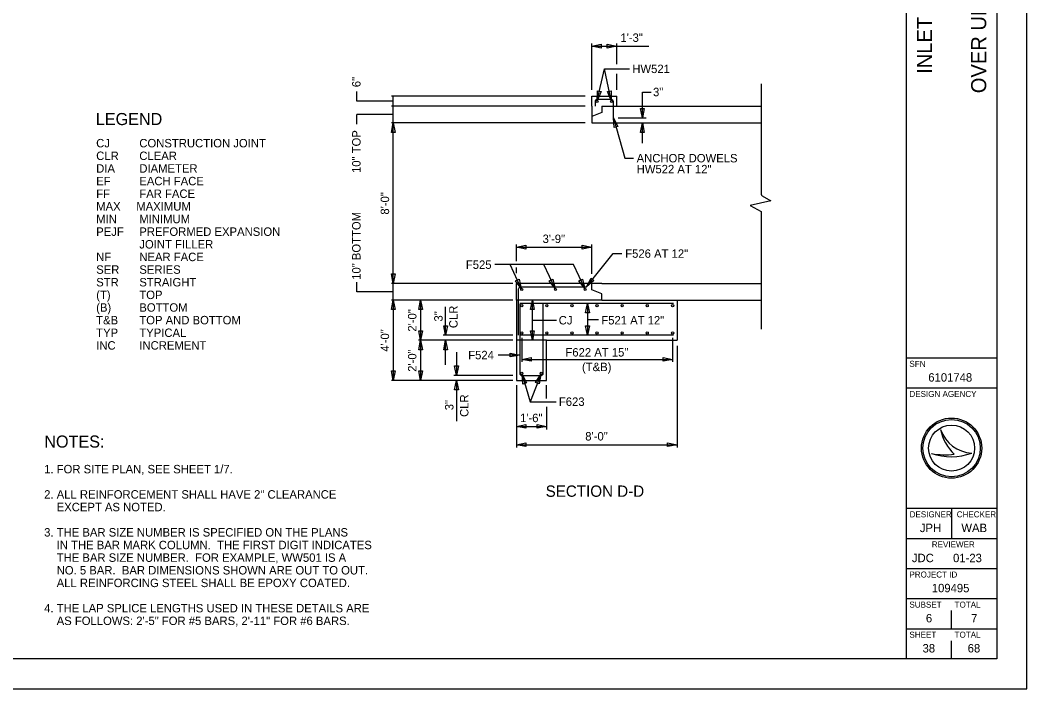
# Model space of a CAD drawing. Extents: x -375 to 456, y -77 to 177.
# Drawn here: x 51.9 to 102, y -77 to -43.6 of the extents above; entities that cross this region are included whole.
import ezdxf

# ---------------------------------------------------------------- set-up
doc = ezdxf.new("R2010")
doc.units = 0
for name, color, linetype in [('BR_P_Gen_Text', 7, 'Continuous'), ('BR_P_Slab_Reinforcing', 7, 'Continuous'), ('BR_P_Sub_Deep_Reinforcing', 7, 'Continuous'), ('DR_P_Culvert', 7, 'Continuous'), ('SH_Border', 7, 'Continuous'), ('SH_Cut_Line', 7, 'Continuous'), ('SH_Data', 7, 'Continuous'), ('TX_P_1', 7, 'Continuous')]:
    doc.layers.add(name, color=color, linetype=linetype)

msp = doc.modelspace()

# ---------------------------------------------------------------- linework, layer by layer
at = {"layer": 'BR_P_Gen_Text'}
for points in [[(80.797, -44.844), (80.797, -45.033), (80.325, -44.939)], [(81.102, -45.033), (81.102, -44.844), (81.575, -44.939)], [(80.618, -47.166), (80.803, -47.208), (80.604, -47.647)], [(81.109, -47.204), (81.294, -47.165), (81.299, -47.647)], [(82.758, -48.044), (82.947, -48.044), (82.853, -48.517)], [(81.628, -48.946), (81.446, -48.997), (81.408, -48.517)], [(70.539, -49.239), (70.35, -49.239), (70.445, -48.767)], [(82.947, -49.239), (82.758, -49.239), (82.853, -48.767)], [(77.047, -54.867), (77.047, -55.056), (76.575, -54.961)], [(79.852, -55.056), (79.852, -54.867), (80.325, -54.961)], [(70.35, -56.294), (70.539, -56.294), (70.445, -56.767)], [(76.534, -56.629), (76.705, -56.549), (76.819, -57.018)], [(78.213, -56.629), (78.384, -56.549), (78.498, -57.018)], [(79.691, -56.629), (79.862, -56.549), (79.976, -57.018)], [(80.292, -56.505), (80.44, -56.622), (80.072, -56.933)], [(70.539, -58.073), (70.35, -58.073), (70.445, -57.6)], [(71.9, -58.073), (71.711, -58.073), (71.806, -57.6)], [(77.468, -58.073), (77.279, -58.073), (77.373, -57.6)], [(80.212, -58.239), (80.023, -58.239), (80.118, -57.767)], [(71.711, -59.128), (71.9, -59.128), (71.806, -59.6)], [(72.957, -58.878), (73.146, -58.878), (73.051, -59.35)], [(77.279, -59.128), (77.468, -59.128), (77.373, -59.6)], [(80.023, -58.878), (80.212, -58.878), (80.118, -59.35)], [(71.9, -60.073), (71.711, -60.073), (71.806, -59.6)], [(73.146, -60.073), (72.957, -60.073), (73.051, -59.6)], [(76.269, -60.431), (76.269, -60.242), (76.742, -60.336)], [(77.314, -60.456), (77.314, -60.645), (76.842, -60.55)], [(83.882, -60.645), (83.882, -60.456), (84.355, -60.55)], [(70.35, -61.128), (70.539, -61.128), (70.445, -61.6)], [(71.711, -61.128), (71.9, -61.128), (71.806, -61.6)], [(73.497, -60.878), (73.686, -60.878), (73.591, -61.35)], [(73.686, -62.073), (73.497, -62.073), (73.591, -61.6)], [(77.084, -61.727), (76.903, -61.782), (76.857, -61.302)], [(77.707, -61.776), (77.531, -61.708), (77.789, -61.301)], [(77.047, -63.795), (77.047, -63.984), (76.575, -63.889)], [(77.602, -63.984), (77.602, -63.795), (78.075, -63.889)], [(77.047, -64.71), (77.047, -64.899), (76.575, -64.805)], [(84.102, -64.899), (84.102, -64.71), (84.575, -64.805)]]:
    msp.add_lwpolyline(points, close=True, dxfattribs=at)
at = {"layer": 'BR_P_Slab_Reinforcing'}
for centre in [(80.592, -47.7), (81.31, -47.7), (76.842, -57.067), (78.521, -57.067), (79.998, -57.067), (76.842, -57.874), (78.092, -57.874), (79.342, -57.874), (80.592, -57.874), (81.842, -57.874), (83.092, -57.874), (84.355, -57.874), (76.842, -59.236), (78.092, -59.236), (79.342, -59.236), (80.592, -59.236), (81.842, -59.236), (83.092, -59.236), (84.355, -59.236), (76.842, -61.25), (77.808, -61.25)]:
    msp.add_circle(centre, 0.0542, dxfattribs=at)
at = {"layer": 'BR_P_Sub_Deep_Reinforcing'}
for p, q in [((81.308, -47.6), (80.592, -47.6)), ((80.492, -47.7), (80.492, -47.933)), ((81.408, -48.517), (81.408, -47.7)), ((76.682, -59.35), (76.682, -57.033)), ((76.782, -56.933), (80.072, -56.933)), ((84.408, -57.767), (76.742, -57.767)), ((76.742, -57.805), (76.742, -61.25)), ((77.908, -61.25), (77.908, -57.805)), ((84.408, -59.35), (76.742, -59.35)), ((76.842, -61.35), (77.808, -61.35))]:
    msp.add_line(p, q, dxfattribs=at)
for centre, start, end in [((80.592, -47.7), 90, 180), ((81.308, -47.7), 0, 90), ((76.782, -57.033), 90, 180), ((76.842, -61.25), 180, 270), ((77.808, -61.25), 270, 360)]:
    msp.add_arc(centre, 0.1, start, end, dxfattribs=at)
at = {"layer": 'DR_P_Culvert'}
for p, q in [((88.765, -46.818), (88.765, -52.312)), ((80.325, -47.933), (80.325, -47.433)), ((80.325, -47.433), (81.575, -47.433)), ((81.575, -47.933), (81.575, -47.433)), ((80.325, -47.933), (80.325, -48.454)), ((80.825, -47.933), (88.765, -47.933)), ((80.825, -47.933), (80.825, -48.246)), ((80.825, -48.246), (80.325, -48.454)), ((80.325, -48.454), (80.325, -48.767)), ((80.325, -48.767), (88.765, -48.767)), ((80.825, -56.767), (76.575, -56.767)), ((76.575, -57.6), (76.575, -56.767)), ((80.325, -57.079), (80.325, -56.767)), ((80.825, -57.288), (80.325, -57.079)), ((80.825, -56.767), (88.765, -56.767)), ((76.575, -57.6), (76.575, -61.6)), ((80.825, -57.6), (76.575, -57.6)), ((80.825, -57.6), (80.825, -57.288)), ((80.825, -57.6), (88.765, -57.6)), ((84.575, -57.6), (84.575, -59.6)), ((78.075, -59.6), (76.575, -59.6)), ((78.075, -61.6), (78.075, -59.6)), ((78.075, -59.6), (84.575, -59.6)), ((76.575, -61.6), (78.075, -61.6))]:
    msp.add_line(p, q, dxfattribs=at)
msp.add_lwpolyline([(88.816, -52.399), (89.255, -52.643), (88.216, -52.89), (88.765, -53.176), (88.765, -59.049)], dxfattribs=at)
msp.add_arc((88.865, -52.312), 0.1, 180, 240.8946, dxfattribs=at)
at = {"layer": 'SH_Border'}
for p, q in [((96, -75.474), (96, -12.474)), ((96, -60.474), (100.5, -60.474)), ((96, -61.974), (100.5, -61.974)), ((96, -67.974), (100.5, -67.974)), ((98.25, -67.974), (98.25, -69.474)), ((96, -69.474), (100.5, -69.474)), ((96, -70.974), (100.5, -70.974)), ((96, -72.474), (100.5, -72.474)), ((96, -73.974), (100.5, -73.974))]:
    msp.add_line(p, q, dxfattribs=at)
msp.add_lwpolyline([(4.5, -12.474), (100.5, -12.474), (100.5, -75.474), (4.5, -75.474)], close=True, dxfattribs=at)
at = {"layer": 'SH_Cut_Line'}
msp.add_lwpolyline([(0, -76.974), (102, -76.974), (102, -10.974), (0, -10.974)], close=True, dxfattribs=at)
at = {"layer": 'SH_Data'}
for p, q in [((97.702, -64.045), (97.702, -64.045)), ((98.25, -64.974), (98.25, -64.974)), ((97.252, -65.245), (97.251, -65.245)), ((99.262, -65.218), (99.262, -65.218)), ((98.25, -73.974), (98.25, -73.074)), ((98.25, -75.474), (98.25, -74.574)), ((97.125, -74.949), (97.125, -74.949))]:
    msp.add_line(p, q, dxfattribs=at)
for radius in [1.5, 1.43, 1.43, 1.147]:
    msp.add_circle((98.25, -64.974), radius, dxfattribs=at)
for centre, radius, start, end in [((99.348, -63.481), 1.74, 198.9257, 198.9319), ((100.04, -63.563), 2.387, 191.6379, 191.6421), ((99.348, -63.481), 1.74, 198.9319, 267.1657), ((100.04, -63.563), 2.387, 191.6421, 226.0947), ((98.218, -62.364), 3.039, 251.4527, 251.4576), ((98.218, -62.364), 3.039, 251.4576, 290.0832), ((97.944, -61.511), 3.798, 259.4964, 259.4995), ((97.944, -61.511), 3.798, 259.4995, 276.6672)]:
    msp.add_arc(centre, radius, start, end, dxfattribs=at)
at = {"layer": 'TX_P_1'}
for p, q in [((80.325, -47.119), (80.325, -44.808)), ((80.325, -44.939), (83.164, -44.939)), ((81.575, -45.837), (81.575, -44.808)), ((80.604, -47.647), (80.969, -46.072)), ((81.299, -47.647), (80.969, -46.072)), ((80.969, -46.072), (82.208, -46.072)), ((81.575, -47.119), (81.575, -46.322)), ((68.625, -47.683), (68.625, -47.197)), ((80.008, -47.433), (70.351, -47.433)), ((70.445, -47.933), (70.445, -47.433)), ((82.853, -47.226), (83.285, -47.226)), ((82.853, -48.517), (82.853, -47.226)), ((70.445, -47.683), (68.625, -47.683)), ((80.008, -47.933), (70.351, -47.933)), ((70.445, -48.767), (70.445, -47.933)), ((70.445, -48.35), (68.625, -48.35)), ((68.625, -48.836), (68.625, -48.35)), ((81.408, -48.517), (81.975, -50.524)), ((81.636, -48.517), (83.032, -48.517)), ((80.008, -48.767), (70.351, -48.767)), ((70.445, -56.767), (70.445, -48.767)), ((82.853, -49.774), (82.853, -48.767)), ((81.975, -50.524), (82.407, -50.524)), ((76.575, -55.652), (76.575, -54.827)), ((76.575, -54.961), (80.325, -54.961)), ((80.325, -56.29), (80.325, -54.827)), ((80.072, -56.933), (81.388, -55.278)), ((81.388, -55.278), (81.819, -55.278)), ((79.423, -55.83), (75.493, -55.83)), ((76.819, -57.018), (76.266, -55.83)), ((76.575, -56.247), (76.575, -55.976)), ((78.498, -57.018), (77.945, -55.83)), ((79.976, -57.018), (79.423, -55.83)), ((68.625, -57.183), (68.625, -56.697)), ((76.391, -56.767), (70.351, -56.767)), ((70.445, -57.6), (70.445, -56.767)), ((70.445, -57.183), (68.625, -57.183)), ((76.391, -57.6), (70.351, -57.6)), ((70.445, -57.6), (70.445, -61.6)), ((71.806, -57.6), (71.806, -59.6)), ((77.373, -59.6), (77.373, -57.6)), ((73.051, -59.35), (73.051, -57.934)), ((80.118, -57.767), (80.118, -59.35)), ((77.373, -58.6), (78.569, -58.6)), ((80.118, -58.558), (80.671, -58.558)), ((76.391, -59.6), (71.703, -59.6)), ((71.806, -59.6), (71.806, -61.6)), ((76.391, -59.35), (72.928, -59.35)), ((73.051, -60.822), (73.051, -59.6)), ((76.842, -59.473), (76.842, -60.681)), ((84.355, -59.473), (84.355, -60.681)), ((84.575, -59.879), (84.575, -64.941)), ((73.591, -60.193), (73.591, -61.35)), ((76.742, -60.336), (75.672, -60.336)), ((76.842, -60.55), (84.355, -60.55)), ((76.391, -61.6), (70.351, -61.6)), ((76.391, -61.35), (73.463, -61.35)), ((73.591, -61.6), (73.591, -63.63)), ((76.857, -61.302), (77.267, -62.659)), ((77.789, -61.301), (77.267, -62.659)), ((76.575, -61.841), (76.575, -64.941)), ((78.075, -62.503), (78.075, -61.841)), ((77.267, -62.659), (78.554, -62.659)), ((78.075, -62.911), (78.075, -64.042)), ((76.575, -63.889), (78.075, -63.889)), ((76.575, -64.805), (84.575, -64.805))]:
    msp.add_line(p, q, dxfattribs=at)

# ---------------------------------------------------------------- texts
at = {"layer": 'SH_Data'}
for s, p in [('OVER UNNAMED TRIBUTARY OF DUCK CREEK', (99.975, -47.286)), ('INLET WINGWALL AND FOOTING DETAILS', (97.275, -46.319))]:
    msp.add_text(s, height=0.75, rotation=90, dxfattribs=at).set_placement(p)
for s, height, p in [('LEGEND', 0.6022, (55.627, -48.874)), ('SFN', 0.3, (96.15, -60.924)), ('6101748', 0.42, (97.09, -61.659)), ('DESIGN AGENCY', 0.3, (96.15, -62.424)), ('NOTES:', 0.6022, (53.061, -64.948)), ('SECTION D-D', 0.56461, (78.032, -67.401)), ('DESIGNER', 0.3, (96.162, -68.424)), ('CHECKER', 0.3, (98.506, -68.424)), ('JPH', 0.42, (96.67, -69.159)), ('WAB', 0.42, (98.738, -69.159)), ('REVIEWER', 0.3, (97.265, -69.924)), ('JDC', 0.42, (96.274, -70.659)), ('01-23', 0.42, (98.323, -70.659)), ('PROJECT ID', 0.3, (96.15, -71.424)), ('109495', 0.42, (97.264, -72.159)), ('SUBSET', 0.3, (96.15, -72.924)), ('TOTAL', 0.3, (98.4, -72.924)), ('6', 0.42, (96.97, -73.659)), ('7', 0.42, (99.223, -73.659)), ('SHEET', 0.3, (96.15, -74.424)), ('TOTAL', 0.3, (98.4, -74.424)), ('38', 0.42, (96.803, -75.159)), ('68', 0.42, (99.053, -75.159))]:
    msp.add_text(s, height=height, dxfattribs=at).set_placement(p)
at = {"layer": 'TX_P_1'}
for s, p in [('1\'-3"', (81.755, -44.729)), ('HW521', (82.348, -46.282)), ('3"', (83.381, -47.436)), ('CJ', (55.646, -49.985)), ('   CONSTRUCTION JOINT', (57.326, -49.985)), ('CLR', (55.646, -50.615)), ('   CLEAR', (57.326, -50.615)), ('ANCHOR DOWELS', (82.564, -50.734)), ('DIA', (55.646, -51.245)), ('   DIAMETER', (57.326, -51.245)), ('HW522 AT 12"', (82.564, -51.278)), ('EF', (55.646, -51.875)), ('   EACH FACE', (57.326, -51.875)), ('FF', (55.646, -52.505)), ('   FAR FACE', (57.326, -52.505)), ('MAX     MAXIMUM', (55.646, -53.135)), ('MIN', (55.646, -53.765)), ('   MINIMUM', (57.326, -53.765)), ('PEJF', (55.646, -54.395)), ('   PREFORMED EXPANSION', (57.326, -54.395)), ('   JOINT FILLER', (57.326, -55.025)), ('3\'-9"', (77.88, -54.751)), ('F526 AT 12"', (81.995, -55.488)), ('NF', (55.646, -55.655)), ('   NEAR FACE', (57.326, -55.655)), ('F525', (74.058, -56.04)), ('SER ', (55.646, -56.285)), ('   SERIES', (57.326, -56.285)), ('STR', (55.646, -56.915)), ('   STRAIGHT', (57.326, -56.915)), ('(T)', (55.646, -57.545)), ('   TOP', (57.326, -57.545)), ('(B)', (55.646, -58.175)), ('   BOTTOM', (57.326, -58.175)), ('T&B', (55.646, -58.805)), ('   TOP AND BOTTOM', (57.326, -58.805)), ('CJ', (78.683, -58.81)), ('F521 AT 12"', (80.804, -58.81)), ('TYP', (55.646, -59.435)), ('   TYPICAL', (57.326, -59.435)), ('INC', (55.646, -60.065)), ('   INCREMENT', (57.326, -60.065)), ('F524', (74.175, -60.546)), ('F622 AT 15"', (79.018, -60.409)), ('(T&B)', (79.843, -61.137)), ('F623', (78.692, -62.869)), ('1\'-6"', (76.755, -63.679)), ('8\'-0"', (80.005, -64.595)), ('1. FOR SITE PLAN, SEE SHEET 1/7.', (53.054, -66.231)), ('2. ALL REINFORCEMENT SHALL HAVE 2" CLEARANCE', (53.054, -67.491)), ('    EXCEPT AS NOTED.', (53.054, -68.121)), ('3. THE BAR SIZE NUMBER IS SPECIFIED ON THE PLANS', (53.054, -69.381)), ('    IN THE BAR MARK COLUMN.  THE FIRST DIGIT INDICATES', (53.054, -70.011)), ('    THE BAR SIZE NUMBER.  FOR EXAMPLE, WW501 IS A', (53.054, -70.641)), ('    NO. 5 BAR.  BAR DIMENSIONS SHOWN ARE OUT TO OUT.', (53.054, -71.271)), ('    ALL REINFORCING STEEL SHALL BE EPOXY COATED.', (53.054, -71.901)), ('4. THE LAP SPLICE LENGTHS USED IN THESE DETAILS ARE', (53.054, -73.161)), ('    AS FOLLOWS: 2\'-5" FOR #5 BARS, 2\'-11" FOR #6 BARS.', (53.054, -73.791))]:
    msp.add_text(s, height=0.42, dxfattribs=at).set_placement(p)
for s, p in [('6"', (68.814, -46.985)), ('10" TOP', (68.814, -51.261)), ('8\'-0"', (70.235, -53.337)), ('10" BOTTOM', (68.814, -56.586)), ('2\'-0"', (71.596, -59.17)), ('CLR', (73.647, -58.995)), ('3"', (72.901, -58.665)), ('4\'-0"', (70.235, -60.17)), ('2\'-0"', (71.596, -61.17)), ('3"', (73.441, -63.088)), ('CLR', (74.187, -63.418))]:
    msp.add_text(s, height=0.42, rotation=90, dxfattribs=at).set_placement(p)

doc.saveas('drawing.dxf')
